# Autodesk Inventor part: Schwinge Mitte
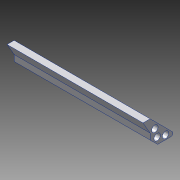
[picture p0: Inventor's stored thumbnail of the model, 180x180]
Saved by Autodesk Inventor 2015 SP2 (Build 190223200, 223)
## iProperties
Created: 2015-08
Part Number: Schwinge Mitte
Material: Aluminium 6061
Document SubType Name: Modeling
Designer: rYan
Mass: 16.0548 g
Surface Area: 33.6694 cm^2
Volume: 5.94623 cm^3
Density: 2.7 g/cm^3
Appearance: Aluminium - flach
Author: rYan
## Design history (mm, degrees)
sketch "Skizze1"
  geometry: L1 (7, 0)-(-1.5, 0); L2 (-1.5, 0)-(-5, 3.5); L3 (-8.291, 12)-(-5, 12); L4 (-5, 12)-(7, 0); L5 (-5, 6.3)-(-5, 3.5); L6 (-5, 6.3)-(-8.291, 12); L7 (0, 14.4)-(0, -2.4) reference; L8 (-11.349, 0)-(10.058, 0) reference; 1 further point; 1 other entity
  constraints: 12 end point, 2 parallel, 2 point on line, 1 collinear, 1 horizontal, 3 other
  dimensions: "d6" = 12 distance between parallel lines of L1 L3; "d7" = 5 distance from line of point (0, 0) L5; "d20" = 45 deg angle of L8 L2; "d21" = 3.5 distance from line of L8 L2.end; "d22" = 30 deg angle of L5 L6; "d23" = 2.8 distance of L5.start L2.end; "d24" = 45 deg angle of L1 L4; "d25" = 8.5 distance of L1.start L1.end
extrude "Extrusion1" new body sketch "Skizze1" stored distance "d4" = 63; taper "d5" = 0 deg
sketch "Skizze2"
  geometry: L1 (0, 7)-(-12, -5) reference; L2 (-12, -5)-(-12, -8.291) reference; L3 (-12, -8.291)-(-6.3, -5) reference; L4 (-6.3, -5)-(-3.5, -5) reference; L5 (-3.5, -5)-(0, -1.5) reference; L6 (0, -1.5)-(0, 7) reference; L7 (-6.95, -2.778)-(-2, 2.172); L8 (-4.475, -0.303)-(-3.061, -1.718); 4 further points
  constraints: 4 end point, 3 coincident, 1 midpoint, 1 perpendicular
  dimensions: "d15" = 2 distance between parallel lines of L1 L7; "d16" = 7 distance of point (-2, 2.172) point (-6.95, -2.778); "d17" = 2 distance from line of L6 L7.end; "d18" = 2 distance of L8.start L8.end
hole "Bohrung1" sketch "Skizze2" at (-3.061, -1.718), (-6.95, -2.778), (-2, 2.172) diameter "d8" = 3; stored, may be unused: countersink angle "d12" = 90 deg, drill point angle "d14" = 118 deg; dims "d9" = 6, "d10" = 4, "d11" = 2, "d13" = 9
mirror "Spiegeln1"
fillet "Rundung1" dims "d19" = 1
node "Volumenkörper1"
node "Projizierte Kontur1"
